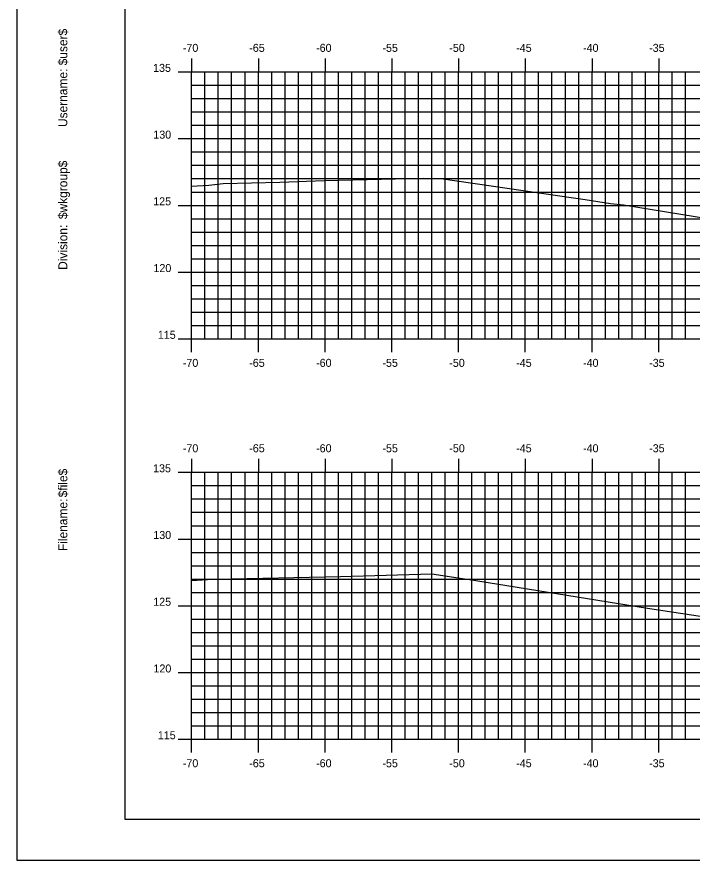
# Model space of a CAD drawing. Extents: x 851517 to 851688, y 365624 to 365734.
# Drawn here: x 851516.7 to 851567.3, y 365624 to 365687.1 of the extents above; entities that cross this region are included whole.
import ezdxf

# ---------------------------------------------------------------- set-up
doc = ezdxf.new("R2010")
doc.units = 0
for name, color, linetype in [('BORDER', 7, 'Continuous'), ('H_V ANNOTATION', 7, 'Continuous'), ('M_Roadway_Centerline', 7, 'Continuous'), ('MAJOR', 7, 'Continuous'), ('MINOR', 7, 'Continuous'), ('PLOT BOUNDARY', 7, 'Continuous'), ('S_Roadway_Centerline', 7, 'Continuous')]:
    doc.layers.add(name, color=color, linetype=linetype)

msp = doc.modelspace()

# ---------------------------------------------------------------- linework, layer by layer
at = {"layer": 'BORDER'}
msp.add_lwpolyline([(851524.766, 365627.027), (851684.766, 365627.027), (851684.766, 365732.027), (851524.766, 365732.027)], close=True, dxfattribs=at)
at = {"layer": 'MAJOR'}
for p, q in [((851529.766, 365684.029), (851529.766, 365683.027)), ((851534.766, 365684.029), (851534.766, 365683.027)), ((851539.766, 365684.029), (851539.766, 365683.027)), ((851544.766, 365684.029), (851544.766, 365683.027)), ((851549.766, 365684.029), (851549.766, 365683.027)), ((851554.766, 365684.029), (851554.766, 365683.027)), ((851559.766, 365684.029), (851559.766, 365683.027)), ((851564.766, 365684.029), (851564.766, 365683.027)), ((851528.764, 365683.027), (851529.766, 365683.027)), ((851529.766, 365683.027), (851669.766, 365683.027)), ((851529.766, 365663.027), (851529.766, 365683.027)), ((851529.766, 365663.027), (851529.766, 365683.027)), ((851529.766, 365683.027), (851669.766, 365683.027)), ((851534.766, 365663.027), (851534.766, 365683.027)), ((851539.766, 365663.027), (851539.766, 365683.027)), ((851544.766, 365663.027), (851544.766, 365683.027)), ((851549.766, 365663.027), (851549.766, 365683.027)), ((851554.766, 365663.027), (851554.766, 365683.027)), ((851559.766, 365663.027), (851559.766, 365683.027)), ((851564.766, 365663.027), (851564.766, 365683.027)), ((851528.764, 365678.027), (851529.766, 365678.027)), ((851529.766, 365678.027), (851669.766, 365678.027)), ((851528.764, 365673.027), (851529.766, 365673.027)), ((851529.766, 365673.027), (851669.766, 365673.027)), ((851528.764, 365668.027), (851529.766, 365668.027)), ((851529.766, 365668.027), (851669.766, 365668.027)), ((851528.764, 365663.027), (851529.766, 365663.027)), ((851529.766, 365663.027), (851669.766, 365663.027)), ((851529.766, 365663.027), (851669.766, 365663.027)), ((851529.766, 365662.025), (851529.766, 365663.027)), ((851534.766, 365662.025), (851534.766, 365663.027)), ((851539.766, 365662.025), (851539.766, 365663.027)), ((851544.766, 365662.025), (851544.766, 365663.027)), ((851549.766, 365662.025), (851549.766, 365663.027)), ((851554.766, 365662.025), (851554.766, 365663.027)), ((851559.766, 365662.025), (851559.766, 365663.027)), ((851564.766, 365662.025), (851564.766, 365663.027)), ((851529.766, 365654.029), (851529.766, 365653.027)), ((851534.766, 365654.029), (851534.766, 365653.027)), ((851539.766, 365654.029), (851539.766, 365653.027)), ((851544.766, 365654.029), (851544.766, 365653.027)), ((851549.766, 365654.029), (851549.766, 365653.027)), ((851554.766, 365654.029), (851554.766, 365653.027)), ((851559.766, 365654.029), (851559.766, 365653.027)), ((851564.766, 365654.029), (851564.766, 365653.027)), ((851528.764, 365653.027), (851529.766, 365653.027)), ((851529.766, 365653.027), (851669.766, 365653.027)), ((851529.766, 365633.027), (851529.766, 365653.027)), ((851529.766, 365633.027), (851529.766, 365653.027)), ((851529.766, 365653.027), (851669.766, 365653.027)), ((851534.766, 365633.027), (851534.766, 365653.027)), ((851539.766, 365633.027), (851539.766, 365653.027)), ((851544.766, 365633.027), (851544.766, 365653.027)), ((851549.766, 365633.027), (851549.766, 365653.027)), ((851554.766, 365633.027), (851554.766, 365653.027)), ((851559.766, 365633.027), (851559.766, 365653.027)), ((851564.766, 365633.027), (851564.766, 365653.027)), ((851528.764, 365648.027), (851529.766, 365648.027)), ((851529.766, 365648.027), (851669.766, 365648.027)), ((851528.764, 365643.027), (851529.766, 365643.027)), ((851529.766, 365643.027), (851669.766, 365643.027)), ((851528.764, 365638.027), (851529.766, 365638.027)), ((851529.766, 365638.027), (851669.766, 365638.027)), ((851528.764, 365633.027), (851529.766, 365633.027)), ((851529.766, 365633.027), (851669.766, 365633.027)), ((851529.766, 365633.027), (851669.766, 365633.027)), ((851529.766, 365632.025), (851529.766, 365633.027)), ((851534.766, 365632.025), (851534.766, 365633.027)), ((851539.766, 365632.025), (851539.766, 365633.027)), ((851544.766, 365632.025), (851544.766, 365633.027)), ((851549.766, 365632.025), (851549.766, 365633.027)), ((851554.766, 365632.025), (851554.766, 365633.027)), ((851559.766, 365632.025), (851559.766, 365633.027)), ((851564.766, 365632.025), (851564.766, 365633.027))]:
    msp.add_line(p, q, dxfattribs=at)
at = {"layer": 'MINOR'}
for p, q in [((851530.766, 365663.027), (851530.766, 365683.027)), ((851531.766, 365663.027), (851531.766, 365683.027)), ((851532.766, 365663.027), (851532.766, 365683.027)), ((851533.766, 365663.027), (851533.766, 365683.027)), ((851535.766, 365663.027), (851535.766, 365683.027)), ((851536.766, 365663.027), (851536.766, 365683.027)), ((851537.766, 365663.027), (851537.766, 365683.027)), ((851538.766, 365663.027), (851538.766, 365683.027)), ((851540.766, 365663.027), (851540.766, 365683.027)), ((851541.766, 365663.027), (851541.766, 365683.027)), ((851542.766, 365663.027), (851542.766, 365683.027)), ((851543.766, 365663.027), (851543.766, 365683.027)), ((851545.766, 365663.027), (851545.766, 365683.027)), ((851546.766, 365663.027), (851546.766, 365683.027)), ((851547.766, 365663.027), (851547.766, 365683.027)), ((851548.766, 365663.027), (851548.766, 365683.027)), ((851550.766, 365663.027), (851550.766, 365683.027)), ((851551.766, 365663.027), (851551.766, 365683.027)), ((851552.766, 365663.027), (851552.766, 365683.027)), ((851553.766, 365663.027), (851553.766, 365683.027)), ((851555.766, 365663.027), (851555.766, 365683.027)), ((851556.766, 365663.027), (851556.766, 365683.027)), ((851557.766, 365663.027), (851557.766, 365683.027)), ((851558.766, 365663.027), (851558.766, 365683.027)), ((851560.766, 365663.027), (851560.766, 365683.027)), ((851561.766, 365663.027), (851561.766, 365683.027)), ((851562.766, 365663.027), (851562.766, 365683.027)), ((851563.766, 365663.027), (851563.766, 365683.027)), ((851565.766, 365663.027), (851565.766, 365683.027)), ((851566.766, 365663.027), (851566.766, 365683.027)), ((851529.766, 365682.027), (851669.766, 365682.027)), ((851529.766, 365682.027), (851530.768, 365682.027)), ((851529.766, 365681.027), (851669.766, 365681.027)), ((851529.766, 365681.027), (851530.768, 365681.027)), ((851529.766, 365680.027), (851669.766, 365680.027)), ((851529.766, 365680.027), (851530.768, 365680.027)), ((851529.766, 365679.027), (851669.766, 365679.027)), ((851529.766, 365679.027), (851530.768, 365679.027)), ((851529.766, 365677.027), (851669.766, 365677.027)), ((851529.766, 365677.027), (851530.768, 365677.027)), ((851529.766, 365676.027), (851669.766, 365676.027)), ((851529.766, 365676.027), (851530.768, 365676.027)), ((851529.766, 365675.027), (851669.766, 365675.027)), ((851529.766, 365675.027), (851530.768, 365675.027)), ((851529.766, 365674.027), (851669.766, 365674.027)), ((851529.766, 365674.027), (851530.768, 365674.027)), ((851529.766, 365672.027), (851669.766, 365672.027)), ((851529.766, 365672.027), (851530.768, 365672.027)), ((851529.766, 365671.027), (851669.766, 365671.027)), ((851529.766, 365671.027), (851530.768, 365671.027)), ((851529.766, 365670.027), (851669.766, 365670.027)), ((851529.766, 365670.027), (851530.768, 365670.027)), ((851529.766, 365669.027), (851669.766, 365669.027)), ((851529.766, 365669.027), (851530.768, 365669.027)), ((851529.766, 365667.027), (851669.766, 365667.027)), ((851529.766, 365667.027), (851530.768, 365667.027)), ((851529.766, 365666.027), (851669.766, 365666.027)), ((851529.766, 365666.027), (851530.768, 365666.027)), ((851529.766, 365665.027), (851669.766, 365665.027)), ((851529.766, 365665.027), (851530.768, 365665.027)), ((851529.766, 365664.027), (851669.766, 365664.027)), ((851529.766, 365664.027), (851530.768, 365664.027)), ((851530.766, 365633.027), (851530.766, 365653.027)), ((851531.766, 365633.027), (851531.766, 365653.027)), ((851532.766, 365633.027), (851532.766, 365653.027)), ((851533.766, 365633.027), (851533.766, 365653.027)), ((851535.766, 365633.027), (851535.766, 365653.027)), ((851536.766, 365633.027), (851536.766, 365653.027)), ((851537.766, 365633.027), (851537.766, 365653.027)), ((851538.766, 365633.027), (851538.766, 365653.027)), ((851540.766, 365633.027), (851540.766, 365653.027)), ((851541.766, 365633.027), (851541.766, 365653.027)), ((851542.766, 365633.027), (851542.766, 365653.027)), ((851543.766, 365633.027), (851543.766, 365653.027)), ((851545.766, 365633.027), (851545.766, 365653.027)), ((851546.766, 365633.027), (851546.766, 365653.027)), ((851547.766, 365633.027), (851547.766, 365653.027)), ((851548.766, 365633.027), (851548.766, 365653.027)), ((851550.766, 365633.027), (851550.766, 365653.027)), ((851551.766, 365633.027), (851551.766, 365653.027)), ((851552.766, 365633.027), (851552.766, 365653.027)), ((851553.766, 365633.027), (851553.766, 365653.027)), ((851555.766, 365633.027), (851555.766, 365653.027)), ((851556.766, 365633.027), (851556.766, 365653.027)), ((851557.766, 365633.027), (851557.766, 365653.027)), ((851558.766, 365633.027), (851558.766, 365653.027)), ((851560.766, 365633.027), (851560.766, 365653.027)), ((851561.766, 365633.027), (851561.766, 365653.027)), ((851562.766, 365633.027), (851562.766, 365653.027)), ((851563.766, 365633.027), (851563.766, 365653.027)), ((851565.766, 365633.027), (851565.766, 365653.027)), ((851566.766, 365633.027), (851566.766, 365653.027)), ((851529.766, 365652.027), (851669.766, 365652.027)), ((851529.766, 365652.027), (851530.768, 365652.027)), ((851529.766, 365651.027), (851669.766, 365651.027)), ((851529.766, 365651.027), (851530.768, 365651.027)), ((851529.766, 365650.027), (851669.766, 365650.027)), ((851529.766, 365650.027), (851530.768, 365650.027)), ((851529.766, 365649.027), (851669.766, 365649.027)), ((851529.766, 365649.027), (851530.768, 365649.027)), ((851529.766, 365647.027), (851669.766, 365647.027)), ((851529.766, 365647.027), (851530.768, 365647.027)), ((851529.766, 365646.027), (851669.766, 365646.027)), ((851529.766, 365646.027), (851530.768, 365646.027)), ((851529.766, 365645.027), (851669.766, 365645.027)), ((851529.766, 365645.027), (851530.768, 365645.027)), ((851529.766, 365644.027), (851669.766, 365644.027)), ((851529.766, 365644.027), (851530.768, 365644.027)), ((851529.766, 365642.027), (851669.766, 365642.027)), ((851529.766, 365642.027), (851530.768, 365642.027)), ((851529.766, 365641.027), (851669.766, 365641.027)), ((851529.766, 365641.027), (851530.768, 365641.027)), ((851529.766, 365640.027), (851669.766, 365640.027)), ((851529.766, 365640.027), (851530.768, 365640.027)), ((851529.766, 365639.027), (851669.766, 365639.027)), ((851529.766, 365639.027), (851530.768, 365639.027)), ((851529.766, 365637.027), (851669.766, 365637.027)), ((851529.766, 365637.027), (851530.768, 365637.027)), ((851529.766, 365636.027), (851669.766, 365636.027)), ((851529.766, 365636.027), (851530.768, 365636.027)), ((851529.766, 365635.027), (851669.766, 365635.027)), ((851529.766, 365635.027), (851530.768, 365635.027)), ((851529.766, 365634.027), (851669.766, 365634.027)), ((851529.766, 365634.027), (851530.768, 365634.027))]:
    msp.add_line(p, q, dxfattribs=at)
at = {"layer": 'PLOT BOUNDARY'}
msp.add_lwpolyline([(851516.673, 365623.968), (851686.673, 365623.968), (851686.673, 365733.968), (851516.673, 365733.968)], close=True, dxfattribs=at)
at = {"layer": 'S_Roadway_Centerline'}
for points in [[(851529.766, 365674.47), (851531.059, 365674.545), (851532.14, 365674.659), (851536.371, 365674.776), (851539.714, 365674.887), (851547.163, 365675.073), (851548.433, 365675.046), (851558.366, 365673.597), (851559.256, 365673.471), (851561.145, 365673.154), (851562.116, 365673.068), (851571.793, 365671.502)], [(851529.766, 365644.928), (851531.351, 365645.01), (851531.409, 365645.015), (851531.419, 365645.016), (851531.436, 365645.016), (851531.516, 365645.02), (851531.614, 365645.02), (851540.91, 365645.227), (851547.758, 365645.41), (851550.383, 365645.031), (851550.433, 365645.023), (851563.919, 365642.847), (851569.683, 365641.974)]]:
    msp.add_lwpolyline(points, dxfattribs=at)

# ---------------------------------------------------------------- texts
at = {"layer": 'BORDER'}
for s, p in [('$user$', (851520.451, 365683.518)), ('Username:', (851520.451, 365678.895)), ('$wkgroup$', (851520.451, 365671.996)), ('Division:', (851520.451, 365668.193)), ('$file$', (851520.451, 365651.152)), ('Filename:', (851520.451, 365647.125))]:
    msp.add_text(s, height=0.6696, rotation=90, dxfattribs=at).set_placement(p)
at = {"layer": 'H_V ANNOTATION'}
for s, p in [('-70', (851529.107, 365684.527)), ('-65', (851534.083, 365684.527)), ('-60', (851539.091, 365684.527)), ('-55', (851544.062, 365684.527)), ('-50', (851549.07, 365684.527)), ('-45', (851554.083, 365684.527)), ('-40', (851559.091, 365684.527)), ('-35', (851564.046, 365684.527)), ('135', (851526.88, 365683.027)), ('130', (851526.896, 365678.027)), ('125', (851526.89, 365673.027)), ('120', (851526.906, 365668.027)), ('115', (851527.233, 365663.027)), ('-70', (851529.107, 365660.927)), ('-65', (851534.083, 365660.927)), ('-60', (851539.091, 365660.927)), ('-55', (851544.062, 365660.927)), ('-50', (851549.07, 365660.927)), ('-45', (851554.083, 365660.927)), ('-40', (851559.091, 365660.927)), ('-35', (851564.046, 365660.927)), ('-70', (851529.107, 365654.527)), ('-65', (851534.083, 365654.527)), ('-60', (851539.091, 365654.527)), ('-55', (851544.062, 365654.527)), ('-50', (851549.07, 365654.527)), ('-45', (851554.083, 365654.527)), ('-40', (851559.091, 365654.527)), ('-35', (851564.046, 365654.527)), ('135', (851526.88, 365653.027)), ('130', (851526.896, 365648.027)), ('125', (851526.89, 365643.027)), ('120', (851526.906, 365638.027)), ('115', (851527.233, 365633.027)), ('-70', (851529.107, 365630.927)), ('-65', (851534.083, 365630.927)), ('-60', (851539.091, 365630.927)), ('-55', (851544.062, 365630.927)), ('-50', (851549.07, 365630.927)), ('-45', (851554.083, 365630.927)), ('-40', (851559.091, 365630.927)), ('-35', (851564.046, 365630.927))]:
    msp.add_text(s, height=0.6, dxfattribs=at).set_placement(p)
at = {"layer": 'M_Roadway_Centerline'}
for s, p in [('C', (851532.135, 365674.659)), ('L', (851532.14, 365674.651)), ('C', (851531.414, 365645.016)), ('L', (851531.419, 365645.009))]:
    msp.add_text(s, height=0.0146, dxfattribs=at).set_placement(p)
at = {"layer": 'MAJOR'}
for p in [(851529.761, 365663.027), (851529.761, 365633.027)]:
    msp.add_text('-', height=0.006, dxfattribs=at).set_placement(p)

doc.saveas('drawing.dxf')
